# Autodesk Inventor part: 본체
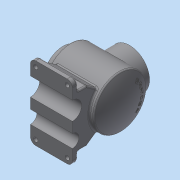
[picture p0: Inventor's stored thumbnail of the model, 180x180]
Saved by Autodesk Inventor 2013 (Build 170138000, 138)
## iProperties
Created: 2018-08
Part Number: 본체
Material: 일반
Document SubType Name: Modeling
Designer: dgall
Density: 1 g/cm^3
Author: dgall
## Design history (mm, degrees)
sketch "스케치4"
  geometry: L1 (0, 0)-(120, 0); L2 (0, 27)-(22, 27); L3 (22, 27)-(22, 40); L4 (22, 40)-(102.163, 40); L5 (102.163, 40)-(102.163, 0); L6 (0, 27)-(0, 38); L7 (0, 38)-(12, 38); L8 (12, 38)-(12, 50); L9 (12, 50)-(108.671, 50); A1 r 106 centre (4, 0) between (110, 0) and (102.163, 40); A2 r 116 centre (4, 0) between (120, 0) and (108.671, 50)
  constraints: 18 end point, 6 parallel, 4 point on circle, 3 point on line, 2 centre point, 2 perpendicular, 1 coincident, 1 horizontal, 1 vertical alignment
  dimensions: "d31" = 80 diameter of L4 L1; "d33" = 116 radius of A2; "d34" = 10 radial gap between concentric circles of A2 A1; "d35" = 100 diameter of L9 L1; "d37" = 76 diameter of L7 L1; "d38" = 54 diameter of L2 L1; "d39" = 12 distance between parallel lines of L8 L6; "d40" = 22 distance between parallel lines of L6 L3; "d41" = 108 distance from line of L1.end L8
revolve "회전2" sketch "스케치4" stored, may be unused: angle "d42" = 90 deg
sketch "스케치5"
  geometry: L1 (20, -82)-(20, -72); L2 (20, -72)-(100, -72); L3 (100, -72)-(100, -82); L4 (100, -82)-(20, -82); L5 (12, -50)-(12, 50) reference; L6 (12, 50)-(108.671, 50) reference; 1 further point
  constraints: 8 end point, 2 parallel, 1 perpendicular, 1 vertical
  dimensions: "d43" = 80 distance between parallel lines of L1 L3; "d45" = 8 distance between parallel lines of L1 L5; "d47" = 10 distance of L1.start L1.end; "d53" = 82 distance from line of L4 point (0, 0)
extrude "돌출3" join sketch "스케치5" stored distance "d48" = 140; taper "d49" = 0 deg
node "작업 평면3"
sketch "스케치6"
  geometry: L1 (0, 10)-(-140, 10) reference; L2 (0, 0)-(0, 10) reference; L3 (0, 0)-(-140, 0) reference; L4 (-140, 10)-(-140, 0) reference; L5 (-106.081, 47.385)-(-120, 27.506); L6 (-120, 27.506)-(-120, 10); L7 (-33.919, 47.385)-(-20, 27.506); L8 (-20, 27.506)-(-20, 10); L9 (-70, 82)-(-70, 0); A1 r 50 centre (-70, 82) between (-106.081, 47.385) and (-33.919, 47.385) reference; 1 further point
  constraints: 10 end point, 2 perpendicular, 2 point on circle, 2 point on line, 1 midpoint, 2 other
  dimensions: "d50" = 20 distance between parallel lines of L4 L6; "d51" = 35 deg angle of L6 L5; "d52" = 19.87884 vertical distance of L7.start L7.end
extrude "돌출4" join sketch "스케치6" stored distance "d54" = 80; taper "d55" = 0 deg
sketch "스케치7"
  geometry: L1 (-70, 82)-(-70, 0); C1 r 50 at (-70, 82) reference; A1 r 12.5 centre (-97.5, 0) between (-85, 0) and (-110, 0); A2 r 17.5 centre (-47.5, 0) between (-30, 0) and (-65, 0); 2 further points
  constraints: 4 point on circle, 2 centre point, 2 end point, 8 other
  dimensions: "d56" = 27.5 distance from line of A1.centre L1; "d58" = 22.5 distance from line of A2.centre L1; "d59" = 12.5 radius of A1; "d60" = 17.5 radius of A2
extrude "돌출5" cut sketch "스케치7" stored distance "d61" = 80; taper "d62" = 0 deg
node "작업 평면4"
sketch "스케치8"
  geometry: L1 (-12, 50)-(-12, -50) reference; C1 r 27 at (-62, 0); C2 r 38 at (-62, 0); 1 further point
  constraints: 2 centre point, 1 coincident, 1 horizontal alignment
  dimensions: "d64" = 50 distance from line of L1 C1.centre; "d65" = 54 diameter of C1; "d66" = 76 diameter of C2
extrude "돌출6" join sketch "스케치8" stored distance "d67" = 80; taper "d68" = 0 deg
extrude "돌출7" cut sketch "스케치8" distance "d69" = 45; taper "d70" = 0 deg
sketch "스케치9" dims "d71" = 65
  geometry: C1 r 38 at (0, 0) reference; 3 further points
  constraints: 2 horizontal alignment, 1 coincident, 2 other
hole "구멍1" sketch "스케치9" at (-32.5, 0) diameter "d73" = 3.242; stored, may be unused: countersink angle "d77" = 90 deg, drill point angle "d79" = 118 deg; dims "d74" = 8, "d75" = 4, "d76" = 2, "d78" = 10
sketch "스케치10" dims "d83" = 65
  geometry: C1 r 38 at (0, 0) reference; C2 r 27 at (0, 0) reference; 2 further points
  constraints: 2 vertical alignment, 1 coincident, 2 other
hole "구멍2" sketch "스케치10" at (0, 32.5) diameter "d85" = 3.242; stored, may be unused: countersink angle "d89" = 90 deg, drill point angle "d91" = 118 deg; dims "d86" = 8, "d87" = 4, "d88" = 2, "d90" = 10
fillet "모깎기1" dims "d95" = 3
fillet "모깎기2" dims "d96" = 10
fillet "모깎기3" dims "d97" = 3
sketch "스케치11"
  geometry: L1 (67, 123)-(7, 123) reference; L2 (77, 93)-(77, 113) reference; L3 (77, 93)-(-3, 93) reference; L4 (-3, 113)-(-3, 93) reference; C1 r 4 at (7, -7); C2 r 4 at (7, 113); C3 r 4 at (67, 113); C4 r 4 at (67, -7); A1 r 7 centre (7, -7) between (0, -7) and (7, -14) reference; A2 r 7 centre (67, -7) between (67, -14) and (74, -7) reference; A3 r 10 centre (7, 113) between (7, 123) and (-3, 113) reference; A4 r 10 centre (67, 113) between (77, 113) and (67, 123) reference; 1 further point
  constraints: 4 centre point, 4 coincident, 3 equal radius
  dimensions: "d98" = 8 diameter of C3
extrude "돌출8" cut sketch "스케치11" distance "d100" = 45; taper "d101" = 0 deg
fillet "모깎기4" dims "d102" = 3
chamfer "모따기1" distance "d103" = 1; stored, may be unused: second distance "d104" = 2, angle "d105" = 45 deg
node "작업 평면6"
  node "작업 평면5"
sketch "스케치12"
  geometry: C1 r 32.5 at (0, 0); 1 further point
  constraints: 1 centre point, 1 coincident, 1 other
  dimensions: "d107" = 65 diameter of C1
feature "엠보싱1" sketch "스케치12" dims "d109" = 0.5, "d110" = 0
node "솔리드2"
pattern_circular "원형 패턴1" dims angle "d81" = 360 deg
pattern_circular "원형 패턴2" dims angle "d93" = 360 deg
node "투영된 루프3"
node "투영된 루프4"
other parameters: "d63" = 65, "d106" = 15
